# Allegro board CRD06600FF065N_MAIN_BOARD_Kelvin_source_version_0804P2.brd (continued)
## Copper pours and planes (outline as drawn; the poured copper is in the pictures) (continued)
N17454238 on BOTTOM (solid shape): 133.1,17.07 134.76,17.07 135.11,16.73 137.05,16.73 137.29,16.49 137.29,15.44 137.29,15.44 137.29,15.26 136.94,14.91 129.33,14.91 128.98,15.26 128.98,16.38 132.08,16.38 132.08,17.02 131.44,17.02 131.44,16.38 128.98,16.38 128.98,16.42 129.25,16.68 130.56,16.68 131.35,17.47 131.35,17.48 132.69,17.48
N17454469 on BOTTOM (solid shape): 151.51,16.44 153.17,16.44 153.52,16.09 155.47,16.09 155.71,15.85 155.71,14.77 155.34,14.4 147.72,14.4 147.4,14.71 147.4,15.62 150.5,15.62 150.5,16.38 149.86,16.38 149.86,15.62 147.4,15.62 147.4,15.8 147.64,16.04 148.91,16.04 149.26,16.39 149.26,16.39 149.72,16.85 151.11,16.85
N17603041 on TOP (solid shape): 130.47,82.29 130.47,66.32 129.76,65.61 125.71,65.61 125.16,66.16 125.16,69.71 124.39,70.48 113.62,70.48 112.29,69.15 112.29,66.42 111.44,65.58 106.48,65.58 106.03,66.03 106.03,75.09 107.01,76.07 117.94,76.07 120.31,78.44 120.31,84.44 121.55,85.68 127.08,85.68
N17603041 on BOTTOM (solid shape): 132.05,80.95 132.05,66.11 130.68,64.74 126.26,64.74 125.16,65.83 125.16,69.1 123.69,70.58 113.55,70.58 112.29,69.31 112.29,65.89 111.48,65.08 106.95,65.08 106.03,66 106.03,75.57 106.84,76.37 117.94,76.37 120.31,78.74 120.31,84 121.84,85.52 127.48,85.52
N17603041 on GND04 (solid shape): 132.05,80.88 132.05,66.09 131.09,65.12 125.9,65.12 125.16,65.86 125.16,69.16 123.75,70.57 113.6,70.57 112.29,69.25 112.29,65.89 111.74,65.34 106.73,65.34 106.03,66.04 106.03,75.4 107.01,76.37 117.94,76.37 120.31,78.74 120.31,84.18 121.56,85.43 127.51,85.43
N17603041 on ART05 (solid shape): 132.05,80.96 132.05,66.12 130.84,64.9 126.1,64.9 125.18,65.82 125.18,66.83 125.17,66.86 125.17,69.14 123.73,70.58 113.52,70.58 112.29,69.34 112.29,65.94 111.45,65.11 106.95,65.11 106.03,66.03 106.03,75.44 106.96,76.37 117.94,76.37 120.31,78.74 120.31,84.18 121.63,85.5 127.51,85.5
N165538091 on TOP (solid shape): 139.49,150.42 139.58,150.36 139.56,150.25 140.64,147.64 141.72,150.25 141.7,150.36 141.79,150.42 144.47,150.42 145.17,149.72 145.17,142 145.16,141.99 145.16,141.84 143.7,140.37 142.23,140.37 141.28,143.09 140.32,140.37 138.96,140.37 138.14,141.2 138.14,149.63 138.93,150.42
N165538091 on ART05 (solid shape): 145.17,149.72 145.17,142 144.11,140.94 138.4,140.94 138.14,141.2 138.14,149.63 138.93,150.42 144.47,150.42
N165801940 on BOTTOM (solid shape): 130.25,167.34 130.25,164.38 130.07,164.21 128.25,164.21 128.09,164.38 128.09,167.28 128.44,167.64 129.94,167.64

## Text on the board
BOTTOM: ARTWORK BOTTOM
Board Geometry/Soldermask Bottom: SOLDERMASK BOTTOM
Package Geometry/Pastemask Bottom: PASTEMASK BOTTOM
Ref Des/Silkscreen Bottom: 14V | SILKSCREEN BOTTOM | + | - | N | L
User.Comments: CR_UNNAMED_3
TOP: ARTWORK TOP | ARTWORK BOTTOM
Board Geometry/Soldermask Top: SOLDERMASK TOP
Package Geometry/Pastemask Top: PASTEMASK TOP
Ref Des/Silkscreen Top: T | M | CRD06600FF065N_K main board | REV 1 2620 | 14V | SILKSCREEN TOP | + | - | N | L
ART02: ARTWORK LAYER02
ART03: ARTWORK LAYER03
GND04: ARTWORK LAYER04
ART05: ARTWORK LAYER05
DIMENSION: Board Cut Out | FAB DRAWING
ASSEMBLY_TOP: PRIMARY SIDE
ASSEMBLY_BOTTOM: SECONDARY SIDE
User.24: FIGURE | SIZE | 12.0 | 32.0 | 39.0 | 40.0 | 47.0 | 49.0 | 51.0 | 59.0 | 59.06 | 70.0 | 87.0 | 122.0 | 158.0 | 79.0x39.0 | 79.0x53.0 | 80.0x60.0 | 157.0x98.0 | 177.17x102.36 | 217.0x138.0 | 222.0x98.0 | 236.0x138.0 | 236.22x173.22 | DRILL CHART: TOP to BOTTOM | ALL UNITS ARE IN MILS | TOLERANCE | +0.0/-0.0 | +3.0/-3.0 | +2.99/-2.99 | PLATED | NON-PLATED | QTY | 516 | 4 | 64 | 60 | 6 | 8 | 28 | 2 | 1 | 3 | 12 | 36
